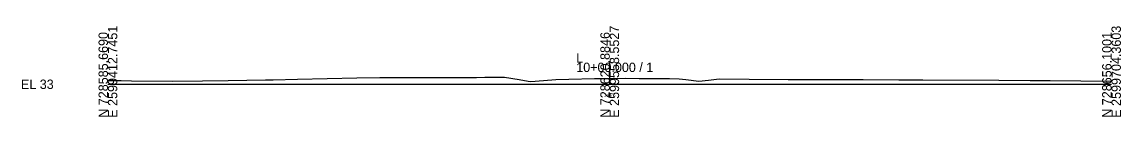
# Model space of a CAD drawing. Extents: x -26 to 3303, y -10 to 9555.
# Drawn here: x -25.7 to 302.8, y -9.7 to 17.3 of the extents above; entities that cross this region are included whole.
import ezdxf

# ---------------------------------------------------------------- set-up
doc = ezdxf.new("R2010")
doc.units = 0
for name, color, linetype in [('Exist Cross Section Cell', 7, 'Continuous'), ('Exist XS Center Line Elevation Label', 7, 'Continuous'), ('Exist XS Ground Line', 7, 'Continuous')]:
    doc.layers.add(name, color=color, linetype=linetype)

msp = doc.modelspace()

# ---------------------------------------------------------------- linework, layer by layer
at = {"layer": 'Exist Cross Section Cell'}
for p, q in [((150, 0), (150, 6.46)), ((0, 0), (150, 0)), ((150, 0), (300, 0))]:
    msp.add_line(p, q, dxfattribs=at)
at = {"layer": 'Exist XS Ground Line'}
msp.add_lwpolyline([(0, 1.08), (3.95, 1.09), (7.05, 1.07), (19.25, 0.91), (28.29, 0.98), (35.94, 1.14), (47.14, 1.3), (49.44, 1.36), (56.71, 1.5), (74.36, 1.95), (81.27, 1.98), (96.04, 1.99), (98.31, 1.99), (99.82, 2.01), (110.16, 2.03), (112.64, 2.1), (116.39, 2.14), (118.53, 2.15), (122.9, 1.45), (125.62, 0.95), (126.35, 0.8), (127.72, 0.9), (133.87, 1.38), (137.8, 1.52), (145.43, 1.68), (150, 1.75), (151.24, 1.77), (154.6, 1.79), (158.76, 1.77), (165.8, 1.75), (167.83, 1.7), (170.78, 1.62), (172.78, 1.4), (176.65, 0.9), (179.57, 1.21), (182.68, 1.64), (191.73, 1.57), (203.33, 1.46), (205.82, 1.38), (209.47, 1.4), (225.79, 1.38), (236.38, 1.36), (240.83, 1.35), (243.61, 1.34), (266.33, 1.2), (275.65, 1.15), (281.62, 1.12), (300, 0.95)], dxfattribs=at)

# ---------------------------------------------------------------- texts
at = {"layer": 'Exist Cross Section Cell'}
for s, p in [('E 2599412.7451', (2.8, -10)), ('E 2599558.5527', (152.8, -10)), ('E 2599704.3603', (302.8, -10)), ('N 728585.6690', (0, -10)), ('N 728620.8846', (150, -10)), ('N 728656.1001', (300, -10))]:
    msp.add_text(s, height=2.8, rotation=90, dxfattribs=at).set_placement(p)
for s, p in [('10+00.000 / 1', (140, 3.66)), ('L', (140, 6.46)), ('EL 33', (-26, -1.4))]:
    msp.add_text(s, height=2.8, dxfattribs=at).set_placement(p)
at = {"layer": 'Exist XS Center Line Elevation Label'}
msp.add_text('34.75', height=1, dxfattribs=at).set_placement((148.27, -3.75))

doc.saveas('drawing.dxf')
